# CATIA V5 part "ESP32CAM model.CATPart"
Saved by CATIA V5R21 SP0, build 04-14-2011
Part number: ESP32CAM model
Bounding box of the stored display mesh (mm): x -13.5 to 13.5, y -20.25 to 20.25, z 0 to 10
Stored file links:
  C:\Users\pc\Desktop\PFA SIMULATION\ESP32CAM model.CATPart
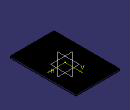
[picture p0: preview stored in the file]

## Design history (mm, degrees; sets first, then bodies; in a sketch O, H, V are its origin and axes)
Body1 (main body)
  Sketch1 on xy-plane, origin (0, 0, 0), H (1, 0, 0), V (0, 1, 0)
    line L1 (-13.5, 20.25) -> (13.5, 20.25)
    line L2 (13.5, 20.25) -> (13.5, -20.25)
    line L3 (13.5, -20.25) -> (-13.5, -20.25)
    line L4 (-13.5, -20.25) -> (-13.5, 20.25)
    length L1 = 27
    length L4 = 40.5
    distance H L3 = 20.25
    distance V L2 = 13.5
    angle L1 L4 = 90
    angle L1 L2 = 90
  Pad1: profile Sketch1, direction (0, 0, 1), length 1
  Sketch2 on end face of Pad1, origin (0, 0, 1), H (1, 0, 0), V (0, 1, 0)
    circle A1 centre (0, 13.25) radius 4
    point P1 (0, 13.25)
    reference projected line E1 (13.5, 20.25) -> (-13.5, 20.25) from edge [face of Pad1 from Sketch1.L1 | end face of Pad1]
    radius A1 = 4
    distance P1 E1 = 7
  Pad2: profile Sketch2, direction (0, 0, 1), length 9
  Sketch3 on end face of Pad1, origin (0, 0, 1), H (1, 0, 0), V (0, 1, 0)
